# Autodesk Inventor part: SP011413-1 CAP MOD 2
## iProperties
Created: 2007-01
Part Number: SP011413-1 CAP MOD 2
Document SubType Name: Modeling
Designer: Andy Moles
Material: ABS Plastic
Density: 1.06 g/cm^3
Mass: 2.83831 g
Surface Area: 22.7841 cm^2
Volume: 2.67765 cm^3
Author: Andy Moles
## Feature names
1. Extrusion1
2. Fillet1
3. Fillet2
4. Extrusion2
5. Extrusion3
6. Fillet3
7. Extrusion4
8. Fillet4
9. Mirror1
10. Extrusion5
